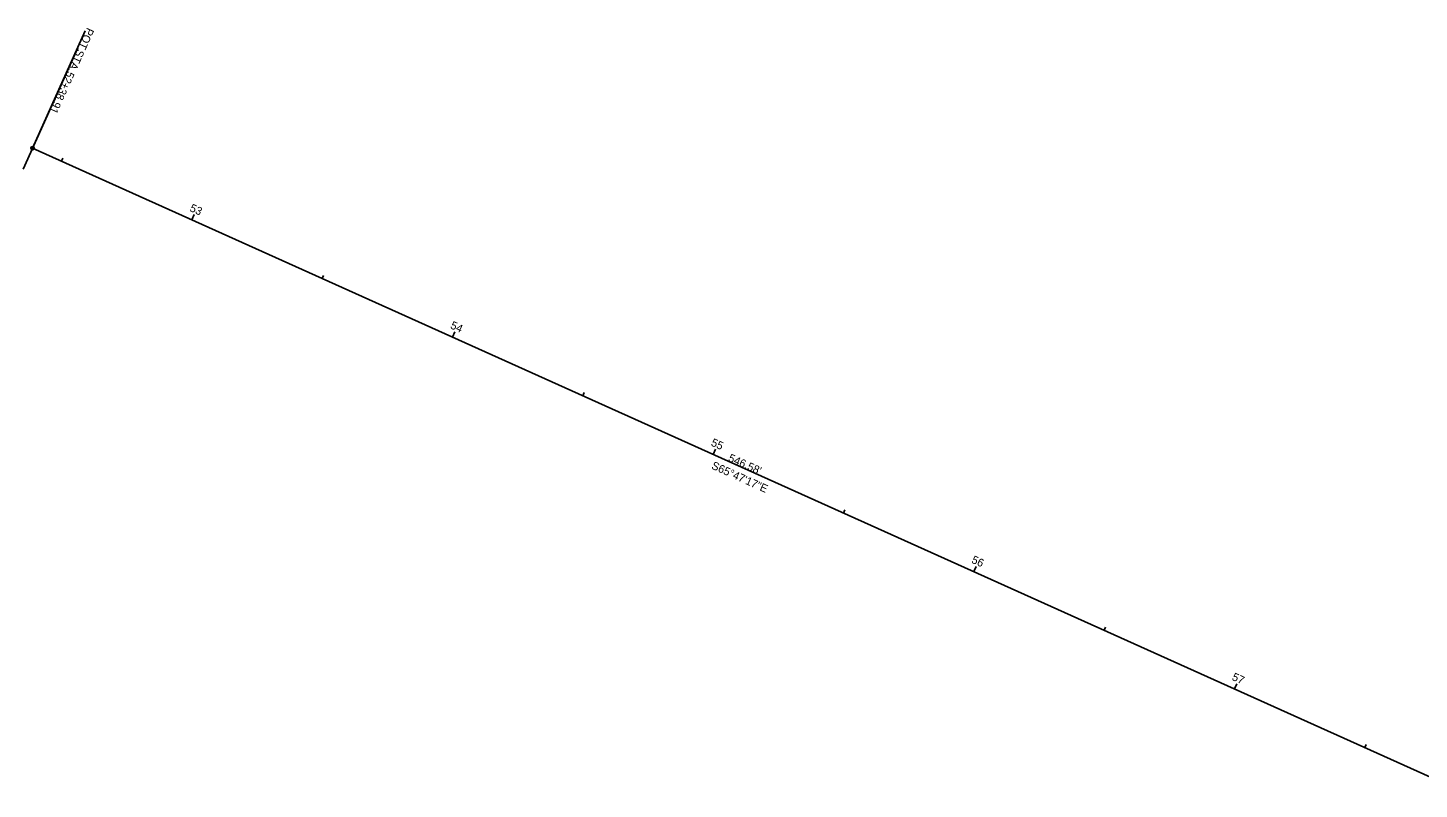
# Model space of a CAD drawing. Extents: x 2199669 to 2203518, y 635127 to 637305.
# Drawn here: x 2201024.3 to 2201511.2, y 635228.5 to 635494.8 of the extents above; entities that cross this region are included whole.
import ezdxf

# ---------------------------------------------------------------- set-up
doc = ezdxf.new("R2010")
doc.units = 0
for name, color, linetype in [('GE_P_Alignment_100_Bearings', 7, 'Continuous'), ('GE_P_Alignment_100_Distances', 7, 'Continuous'), ('RD_P_GR_Lt', 7, 'Continuous'), ('RD_P_GR_Rt', 7, 'Continuous'), ('SC_Scratch1', 7, 'Continuous')]:
    doc.layers.add(name, color=color, linetype=linetype)

msp = doc.modelspace()

# ---------------------------------------------------------------- linework, layer by layer
at = {"layer": 'RD_P_GR_Lt'}
for p, q in [((2201025.98, 635452.69), (2201044.44, 635493.73)), ((2201022.7, 635445.4), (2201041.79, 635487.83))]:
    msp.add_line(p, q, dxfattribs=at)
msp.add_circle((2201025.98, 635452.69), 0.6, dxfattribs=at)
msp.add_circle((2201025.98, 635452.69), 0.6, dxfattribs=at)
at = {"layer": 'RD_P_GR_Rt'}
msp.add_line((2201025.98, 635452.69), (2201524.48, 635228.53), dxfattribs=at)
msp.add_line((2201025.98, 635452.69), (2201524.48, 635228.53), dxfattribs=at)
at = {"layer": 'SC_Scratch1'}
for p, q in [((2201036.1, 635448.14), (2201036.59, 635449.24)), ((2201081.7, 635427.64), (2201082.52, 635429.46)), ((2201127.3, 635407.13), (2201127.79, 635408.23)), ((2201172.9, 635386.63), (2201173.72, 635388.45)), ((2201218.5, 635366.12), (2201219, 635367.22)), ((2201264.11, 635345.62), (2201264.93, 635347.44)), ((2201309.71, 635325.11), (2201310.2, 635326.2)), ((2201355.31, 635304.6), (2201356.13, 635306.43)), ((2201400.91, 635284.1), (2201401.4, 635285.19)), ((2201446.51, 635263.59), (2201447.33, 635265.42)), ((2201492.12, 635243.09), (2201492.61, 635244.18))]:
    msp.add_line(p, q, dxfattribs=at)

# ---------------------------------------------------------------- texts
at = {"layer": 'GE_P_Alignment_100_Bearings'}
msp.add_text('S65°47\'17"E', height=2.8, rotation=335.788, dxfattribs=at).set_placement((2201263.29, 635340.72))
at = {"layer": 'GE_P_Alignment_100_Distances'}
msp.add_text("546.58'", height=2.8, rotation=335.788, dxfattribs=at).set_placement((2201269.16, 635343.39))
at = {"layer": 'RD_P_GR_Lt'}
for s, p in [('POT', (2201045.09, 635495.07)), (' STA. ', (2201042.13, 635488.5)), ('52+38.91', (2201038.26, 635479.88))]:
    msp.add_text(s, height=2.8, rotation=245.788, dxfattribs=at).set_placement(p)
at = {"layer": 'SC_Scratch1'}
for s, p in [('53', (2201080.76, 635430.8)), ('54', (2201171.96, 635389.79)), ('55', (2201263.14, 635348.79)), ('56', (2201354.29, 635307.8)), ('57', (2201445.44, 635266.82))]:
    msp.add_text(s, height=2.8, rotation=335.788, dxfattribs=at).set_placement(p)

doc.saveas('drawing.dxf')
